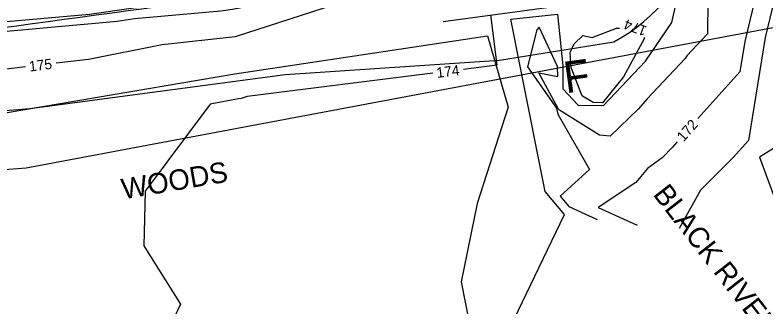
# Model space of a CAD drawing. Extents: x 2086416 to 2115205, y 575507 to 632762.
# Drawn here: x 2111920.5 to 2112066, y 581620.8 to 581677.4 of the extents above; entities that cross this region are included whole.
import ezdxf

# ---------------------------------------------------------------- set-up
doc = ezdxf.new("R2010")
doc.units = 0
for name, color, linetype in [('Default', 7, 'Continuous'), ('DTM Contours Major', 7, 'Continuous'), ('DTM Contours Major Text', 7, 'Continuous'), ('DTM Contours Minor', 7, 'Continuous'), ('DTM Contours Minor Text', 7, 'Continuous'), ('Exist Hydro Stream or Body of Water', 7, 'Continuous'), ('Exist Hydro Stream or Body of Water Text', 7, 'Continuous'), ('Exist Hydrographic FEMA Cross Section', 7, 'Continuous'), ('Exist Right of Way Line', 7, 'Continuous'), ('Exist Vegetation Woods Line', 7, 'Continuous'), ('Exist Vegetation Woods Line Text', 7, 'Continuous'), ('Prop SS Fill Line', 7, 'Continuous'), ('Prop SS Fill Text', 7, 'Continuous')]:
    doc.layers.add(name, color=color, linetype=linetype)

msp = doc.modelspace()

# ---------------------------------------------------------------- linework, layer by layer
at = {"layer": 'Default'}
msp.add_line((2112003.61, 581676.16), (2112036.66, 581680.66), dxfattribs=at)
at = {"layer": 'DTM Contours Major'}
for points in [[(2112026.02, 581688.95), (2112012.75, 581685.87), (2112011.72, 581685.68), (2111992.43, 581681.95), (2111992.08, 581681.89), (2111986.82, 581680.87), (2111963.21, 581673.22), (2111949.06, 581671.62), (2111934.77, 581668.82), (2111928.47, 581668.07)], [(2111922.51, 581667.36), (2111914.6, 581666.41), (2111904.37, 581661.02), (2111870.64, 581651.43), (2111865.11, 581649.26), (2111862.98, 581649.41), (2111825.91, 581645.06)]]:
    msp.add_lwpolyline(points, dxfattribs=at)
at = {"layer": 'DTM Contours Minor'}
for points in [[(2112099.58, 581721.47), (2112099.78, 581716.48), (2112098.96, 581715.12), (2112098.92, 581714.21), (2112096.91, 581702.43), (2112096.94, 581702.35), (2112096.95, 581702.25), (2112096.93, 581702.06), (2112096.43, 581701.23), (2112087.62, 581683.65), (2112083.11, 581676.95), (2112080.12, 581659.33), (2112072.6, 581654.59), (2112064.96, 581649.82), (2112068.33, 581640.74)], [(2112061.21, 581719.46), (2112062.6, 581717.03), (2112064.76, 581713.69), (2112066.89, 581710.24), (2112070.14, 581700.28), (2112072.84, 581697.24), (2112070.63, 581692.11), (2112066.05, 581673.08), (2112062.82, 581653.08), (2112059.86, 581649.8), (2112053.49, 581643.44), (2112049.37, 581635.99)], [(2112067.49, 581694.94), (2112064.51, 581682.38), (2112062.08, 581672.28), (2112061.12, 581666.37), (2112052.96, 581657.34)], [(2112031.77, 581694.58), (2112029.72, 581694.35), (2112012.28, 581690.31), (2112005.11, 581688.97), (2111992.06, 581686.45), (2111982.05, 581684.58), (2111962.56, 581680.8), (2111956.92, 581679.99), (2111943.51, 581678.78), (2111934.94, 581677.55), (2111913.68, 581675.63), (2111907.39, 581674.44), (2111889.3, 581670.89), (2111883.08, 581669.72), (2111859.35, 581665.03), (2111858.2, 581664.94), (2111846.44, 581663.89), (2111842.37, 581663.59), (2111834.55, 581662.91)], [(2112032.78, 581692.79), (2112012.51, 581688.09), (2112008.41, 581687.33), (2111992.25, 581684.2), (2111987.07, 581683.23), (2111962.73, 581678.52), (2111960.43, 581678.19), (2111943.7, 581676.67), (2111940.33, 581676.18), (2111913.84, 581673.8), (2111911.52, 581673.36), (2111889.18, 581668.98), (2111888.94, 581668.85), (2111888.64, 581668.76), (2111861.62, 581658.14), (2111851.19, 581658.87), (2111839.99, 581657.56), (2111837.2, 581658.34)], [(2112054.92, 581680.38), (2112054.84, 581673.74), (2112050.88, 581669.5), (2112050.51, 581669.01), (2112043.14, 581661.15), (2112041.47, 581659.21), (2112036.01, 581653.93), (2112033.92, 581654.13), (2112026.14, 581658.98), (2112025.97, 581659.15), (2112022.13, 581666.23), (2112025.82, 581665.48), (2112025.79, 581667.42), (2112022.23, 581675.07), (2112021.78, 581674.52), (2112019.93, 581667.34), (2112025.55, 581659.33), (2112025.8, 581658.2), (2112031.99, 581647.48), (2112026.31, 581642.3), (2112027.95, 581640.3), (2112033.47, 581637.79)], [(2112012.75, 581677.44), (2112014.01, 581667.67), (2112007.52, 581666.86)], [(2112032.69, 581660.45), (2112030.64, 581661.66), (2112030.53, 581661.77), (2112030.38, 581662.21), (2112028.42, 581667.21), (2112028.36, 581668.11), (2112028.22, 581670.14), (2112029, 581671.84), (2112030.65, 581673.44), (2112032.52, 581673.05), (2112037.22, 581674.88), (2112037.81, 581674.89)], [(2112042.55, 581673.12), (2112042.62, 581672.95), (2112040.17, 581668.38), (2112038.56, 581665.46), (2112034.52, 581660.38), (2112032.69, 581660.45)], [(2112001.57, 581666.12), (2111965.52, 581661.61), (2111964.4, 581661.24), (2111963.9, 581661.19), (2111958.38, 581660.11), (2111945.74, 581643.25), (2111945.53, 581632.64), (2111952.64, 581621.35), (2111948.73, 581613.13), (2111963.74, 581611.46), (2111970.42, 581606.19), (2111976.09, 581595.16), (2111984.65, 581581.25), (2111984.7, 581578.65), (2111987.39, 581578.17), (2111998.82, 581581.21), (2112008.29, 581584.73), (2112005.23, 581606.22), (2112005.78, 581606.97)], [(2112048.99, 581652.84), (2112048.07, 581651.78), (2112046.04, 581649.74), (2112043.25, 581647.63), (2112040.93, 581644.92), (2112033.68, 581640.1), (2112041.2, 581636.69)]]:
    msp.add_lwpolyline(points, dxfattribs=at)
at = {"layer": 'Exist Hydro Stream or Body of Water'}
for points in [[(2112027.13, 581638.7), (2112023.35, 581643.17), (2112018.58, 581667.17), (2112016.71, 581676.59), (2112025.79, 581677.58), (2112026.82, 581667.59), (2112026.82, 581663.09), (2112029.79, 581659.93), (2112034.68, 581659.86), (2112042.82, 581668.45), (2112047.95, 581675.95), (2112050.49, 581687.19), (2112059.54, 581689.87), (2112059.94, 581700.98)], [(2112026.79, 581556.19), (2112027.99, 581568.85), (2112025.16, 581584.18), (2112023.21, 581604.37), (2112017.27, 581618.27), (2112027.13, 581638.7)]]:
    msp.add_lwpolyline(points, dxfattribs=at)
at = {"layer": 'Exist Hydrographic FEMA Cross Section'}
msp.add_lwpolyline([(2112201.88, 581700.22), (2111922.67, 581647.71), (2111776.13, 581636.5), (2111658.78, 581615.59), (2111477.28, 581602.23)], dxfattribs=at)
at = {"layer": 'Exist Right of Way Line'}
msp.add_arc((2119136.65, 528602.9), 53560.67, 97.642388, 97.856215, dxfattribs=at)
at = {"layer": 'Exist Vegetation Woods Line'}
for points in [[(2111785.51, 581656), (2111806.71, 581641.4), (2111833.87, 581646.25), (2111866.92, 581639.44), (2111902.2, 581655.66), (2111963.16, 581666.03), (2112012.17, 581673.36), (2112016.22, 581659.52)], [(2112016.22, 581659.52), (2112010.15, 581640.89), (2112007.07, 581625.66), (2112011.47, 581603.31), (2112014.66, 581580.91), (2112013.34, 581563.73), (2112012.63, 581538.51), (2112010.71, 581519.35), (2112013.56, 581494.84), (2112014.97, 581481.49), (2112022.73, 581466.4), (2112037.51, 581453.75), (2112050.78, 581446.7), (2112062.82, 581439.28), (2112065.18, 581428.19)]]:
    msp.add_lwpolyline(points, dxfattribs=at)
at = {"layer": 'Prop SS Fill Line'}
for p, q in [((2112014.49, 581668.64), (2112036.68, 581672.23)), ((2111972.95, 581665.89), (2112014.49, 581668.64)), ((2111923.38, 581659.31), (2111972.95, 581665.89)), ((2111873.52, 581654.92), (2111923.38, 581659.31))]:
    msp.add_line(p, q, dxfattribs=at)
msp.add_arc((2112020.67, 581702.15), 33.94, 298.1531, 345.6062, dxfattribs=at)

# ---------------------------------------------------------------- texts
at = {"layer": 'DTM Contours Major Text'}
msp.add_text('175', height=2, rotation=6.8056, dxfattribs=at).set_placement((2111923.35, 581666.45))
at = {"layer": 'DTM Contours Minor Text'}
for s, rotation, p in [('174', 159.5009, (2112043.29, 581675.12)), ('174', 7.1325, (2112002.41, 581665.21)), ('172', 48.6477, (2112050.22, 581652.72))]:
    msp.add_text(s, height=2, rotation=rotation, dxfattribs=at).set_placement(p)
at = {"layer": 'Exist Hydro Stream or Body of Water Text'}
msp.add_text('BLACK RIVER', height=4, rotation=307.9408, dxfattribs=at).set_placement((2112044.15, 581642.61))
at = {"layer": 'Exist Vegetation Woods Line Text'}
msp.add_text('WOODS', height=4, rotation=9.6237, dxfattribs=at).set_placement((2111941.53, 581641.65))
at = {"layer": 'Prop SS Fill Text'}
msp.add_text('F', height=6.1, rotation=7.771, dxfattribs=at).set_placement((2112027.4, 581662.23))

doc.saveas('drawing.dxf')
